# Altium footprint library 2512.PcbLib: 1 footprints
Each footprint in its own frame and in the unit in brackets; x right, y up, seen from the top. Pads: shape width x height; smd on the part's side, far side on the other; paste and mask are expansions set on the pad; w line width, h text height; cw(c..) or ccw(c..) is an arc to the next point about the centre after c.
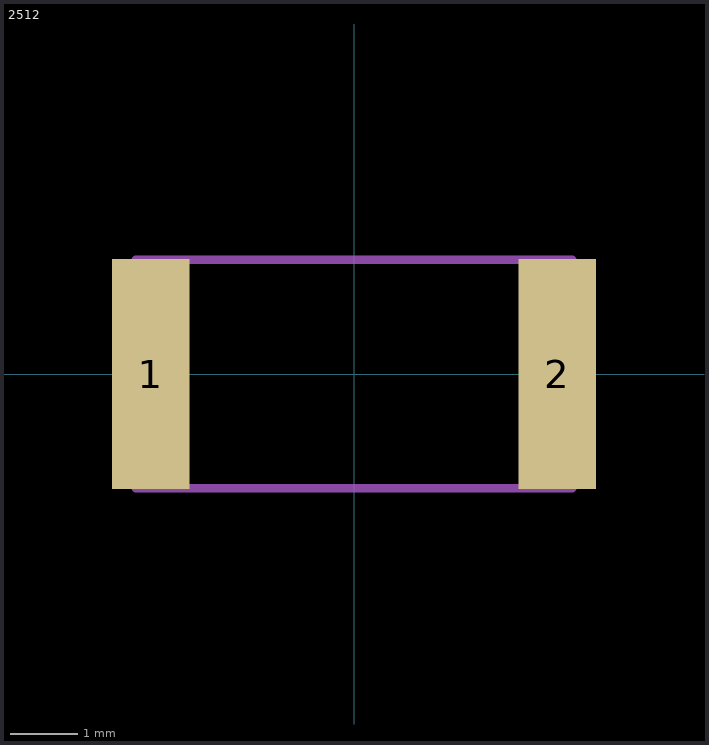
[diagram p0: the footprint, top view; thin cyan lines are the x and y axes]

## 2512 [mm]
pads (2):
  rect 1.16x3.42 smd: 1(-3.025,0) 2(3.025,0)
Assembly Top:
  lines w0.127: -3.25,-1.7 -3.25,1.7 3.25,1.7 3.25,-1.7 -3.25,-1.7
3D body "step_temp.STEP": height 0.75, standoff 0, extent -3.15,-1.55 3.15,1.55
